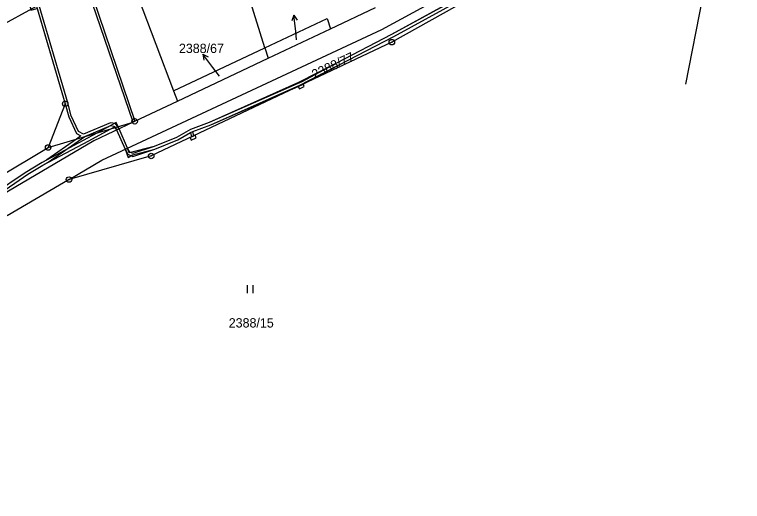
# Model space of a CAD drawing. Extents: x -758836 to -757729, y -1175316 to -1174366.
# Drawn here: x -758462.2 to -758329.3, y -1175257.8 to -1175168.9 of the extents above; entities that cross this region are included whole.
import ezdxf

# ---------------------------------------------------------------- set-up
doc = ezdxf.new("R2010")
doc.units = 0
for name, color, linetype in [('Hranice parcel', 7, 'Continuous'), ('Parcelní čísla', 7, 'Continuous'), ('Pop  PČ popisy', 7, 'Continuous'), ('Věcná břemena k části', 7, 'Continuous'), ('Značky bodu BP', 7, 'Continuous'), ('Značky kultur', 7, 'Continuous')]:
    doc.layers.add(name, color=color, linetype=linetype)

msp = doc.modelspace()

# ---------------------------------------------------------------- linework, layer by layer
at = {"layer": 'Hranice parcel'}
for p, q in [((-758461.57, -1175125.29), (-758440.3, -1175188.4)), ((-758416.54, -1175174.99), (-758422.5, -1175155.82)), ((-758441.44, -1175161.17), (-758433.19, -1175182.83)), ((-758339.68, -1175181.63), (-758336.39, -1175165.01)), ((-758485.2, -1175182.07), (-758458.25, -1175167.38)), ((-758404.56, -1175171.48), (-758396.34, -1175167.59)), ((-758415.95, -1175176.88), (-758404.56, -1175171.48)), ((-758433.19, -1175182.83), (-758416.54, -1175174.99)), ((-758416.54, -1175174.99), (-758415.95, -1175176.88)), ((-758432.48, -1175184.7), (-758415.95, -1175176.88)), ((-758433.19, -1175182.83), (-758432.48, -1175184.7)), ((-758440.3, -1175188.4), (-758432.48, -1175184.7)), ((-758456.12, -1175193.18), (-758440.6, -1175188.57)), ((-758440.3, -1175188.4), (-758440.6, -1175188.57)), ((-758478.03, -1175206.32), (-758456.12, -1175193.18)), ((-758452.3, -1175199.04), (-758463.57, -1175205.69))]:
    msp.add_line(p, q, dxfattribs=at)
for points in [[(-758440.6, -1175188.57), (-758462.14, -1175125.6), (-758461.57, -1175125.29)], [(-758452.3, -1175199.04), (-758446.3, -1175195.5), (-758395.2, -1175171.61), (-758348.62, -1175146.28), (-758329.33, -1175129.34)], [(-758330.11, -1175133.3), (-758340.08, -1175142.92), (-758346.47, -1175147.7), (-758393.35, -1175173.94), (-758437.3, -1175194.73), (-758452.3, -1175199.04)], [(-758458.25, -1175167.38), (-758452.99, -1175185.19), (-758456.12, -1175193.18)], [(-758416.54, -1175174.99), (-758405.13, -1175169.62), (-758404.56, -1175171.48)], [(-758440.6, -1175188.57), (-758447.78, -1175191.94), (-758489.52, -1175216.53), (-758525.18, -1175238.13), (-758543.6, -1175245.98), (-758568.36, -1175253.9), (-758575.95, -1175257.83)]]:
    msp.add_lwpolyline(points, dxfattribs=at)
at = {"layer": 'Pop  PČ popisy'}
for p, q in [((-758411.22, -1175169.01), (-758411.62, -1175170.05)), ((-758410.91, -1175171.99), (-758411.22, -1175169.01)), ((-758411.22, -1175169.01), (-758410.62, -1175169.95)), ((-758410.77, -1175173.5), (-758410.91, -1175171.99)), ((-758426.06, -1175178.54), (-758427.87, -1175176.14)), ((-758427.87, -1175176.14), (-758426.86, -1175176.64)), ((-758427.87, -1175176.14), (-758427.66, -1175177.24)), ((-758424.83, -1175180.15), (-758426.06, -1175178.54))]:
    msp.add_line(p, q, dxfattribs=at)
at = {"layer": 'Věcná břemena k části'}
for points in [[(-758465.13, -1175144.13), (-758458.36, -1175167), (-758459.47, -1175167.31), (-758459.3, -1175167.95), (-758459.26, -1175168.08), (-758458.14, -1175167.76), (-758452.99, -1175185.19), (-758452.35, -1175187.57), (-758450.96, -1175190.61), (-758450.13, -1175191.07), (-758450.93, -1175191.64), (-758456.34, -1175195.44), (-758457.23, -1175195.92), (-758460.29, -1175197.78), (-758466.12, -1175201.71)], [(-758465.62, -1175201.98), (-758459.83, -1175198.08), (-758457.09, -1175196.41), (-758456.08, -1175195.88), (-758449.43, -1175191.19), (-758444.66, -1175189.17), (-758444.11, -1175189.26), (-758443.91, -1175189.55), (-758443.61, -1175189.98), (-758443.15, -1175189.77), (-758443.41, -1175189.4), (-758443.83, -1175188.8), (-758444.72, -1175188.65), (-758449.65, -1175190.77), (-758450.58, -1175190.25), (-758451.89, -1175187.39), (-758452.51, -1175185.05), (-758457.77, -1175167.24), (-758464.65, -1175143.99)], [(-758381, -1175165.69), (-758393.39, -1175172.55), (-758403.45, -1175177.75), (-758409.8, -1175181.17), (-758410.66, -1175181.57), (-758426.7, -1175188.64), (-758430.1, -1175189.87), (-758432.68, -1175191.33), (-758436.78, -1175192.98), (-758441.29, -1175194.17), (-758441.6, -1175193.3), (-758443.15, -1175189.77), (-758443.61, -1175189.98), (-758442.05, -1175193.51), (-758441.49, -1175195.01), (-758440.72, -1175194.53), (-758436.62, -1175193.46), (-758432.42, -1175191.75), (-758430.14, -1175190.47), (-758429.94, -1175191.25), (-758429.48, -1175191.03), (-758429.68, -1175190.25), (-758426.42, -1175189.06), (-758410.46, -1175182.03), (-758409.56, -1175181.61), (-758402.97, -1175178.06), (-758393.01, -1175172.91), (-758380.76, -1175166.13)], [(-758381.28, -1175165.84), (-758393.39, -1175172.55), (-758403.45, -1175177.75), (-758410.4, -1175181.31), (-758426.7, -1175188.64), (-758430.1, -1175189.87), (-758432.68, -1175191.33), (-758436.78, -1175192.98), (-758440.62, -1175194.28), (-758441.21, -1175194.01), (-758441.6, -1175193.3), (-758443.15, -1175189.77), (-758443.61, -1175189.98), (-758442.05, -1175193.51), (-758441.57, -1175194.39), (-758440.64, -1175194.82), (-758436.62, -1175193.46), (-758432.42, -1175191.75), (-758430.14, -1175190.47), (-758429.68, -1175190.25), (-758426.42, -1175189.06), (-758410.18, -1175181.77), (-758402.97, -1175178.06), (-758393.01, -1175172.91), (-758380.76, -1175166.13)]]:
    msp.add_lwpolyline(points, dxfattribs=at)
for points in [[(-758410.46, -1175182.03), (-758410.24, -1175182.49), (-758409.34, -1175182.05), (-758409.56, -1175181.61)], [(-758443.61, -1175189.98), (-758443.15, -1175189.77), (-758443.33, -1175189.38), (-758443.66, -1175188.63), (-758447.07, -1175190.49), (-758448.92, -1175191.5), (-758457.23, -1175195.92), (-758460.29, -1175197.78), (-758466.12, -1175201.71), (-758469.62, -1175204.24), (-758471.22, -1175205.5), (-758474.63, -1175207.39), (-758479, -1175210.33), (-758469.33, -1175204.64), (-758466.05, -1175202.27), (-758465.89, -1175202.61), (-758465.45, -1175202.35), (-758465.62, -1175201.98), (-758459.83, -1175198.08), (-758457.09, -1175196.41), (-758448.68, -1175191.94), (-758444.77, -1175189.81), (-758443.9, -1175189.33), (-758443.82, -1175189.53)], [(-758429.94, -1175191.25), (-758430.18, -1175191.36), (-758429.97, -1175191.81), (-758429.07, -1175191.39), (-758429.28, -1175190.94), (-758429.48, -1175191.03)]]:
    msp.add_lwpolyline(points, close=True, dxfattribs=at)
at = {"layer": 'Značky bodu BP'}
for centre, radius in [((-758393.35, -1175173.94), 0.5), ((-758393.35, -1175173.94), 0.0303), ((-758452.99, -1175185.19), 0.5), ((-758452.99, -1175185.19), 0.0303), ((-758440.3, -1175188.4), 0.5), ((-758440.3, -1175188.4), 0.0303), ((-758456.12, -1175193.18), 0.5), ((-758456.12, -1175193.18), 0.0303), ((-758437.3, -1175194.73), 0.5), ((-758437.3, -1175194.73), 0.0303), ((-758452.3, -1175199.04), 0.5), ((-758452.3, -1175199.04), 0.0303)]:
    msp.add_circle(centre, radius, dxfattribs=at)
at = {"layer": 'Značky kultur'}
for p, q in [((-758419.69, -1175219.81), (-758419.69, -1175218.31)), ((-758418.69, -1175219.81), (-758418.69, -1175218.31))]:
    msp.add_line(p, q, dxfattribs=at)

# ---------------------------------------------------------------- texts
at = {"layer": 'Parcelní čísla'}
for s, p in [('2388/67', (-758432.23, -1175175.92)), ('2388/15', (-758423.13, -1175226.06))]:
    msp.add_text(s, height=1.7, dxfattribs=at).set_placement(p)
msp.add_text('2388/77', height=1.7, rotation=25, dxfattribs=at).set_placement((-758407.49, -1175180.71))

doc.saveas('drawing.dxf')
